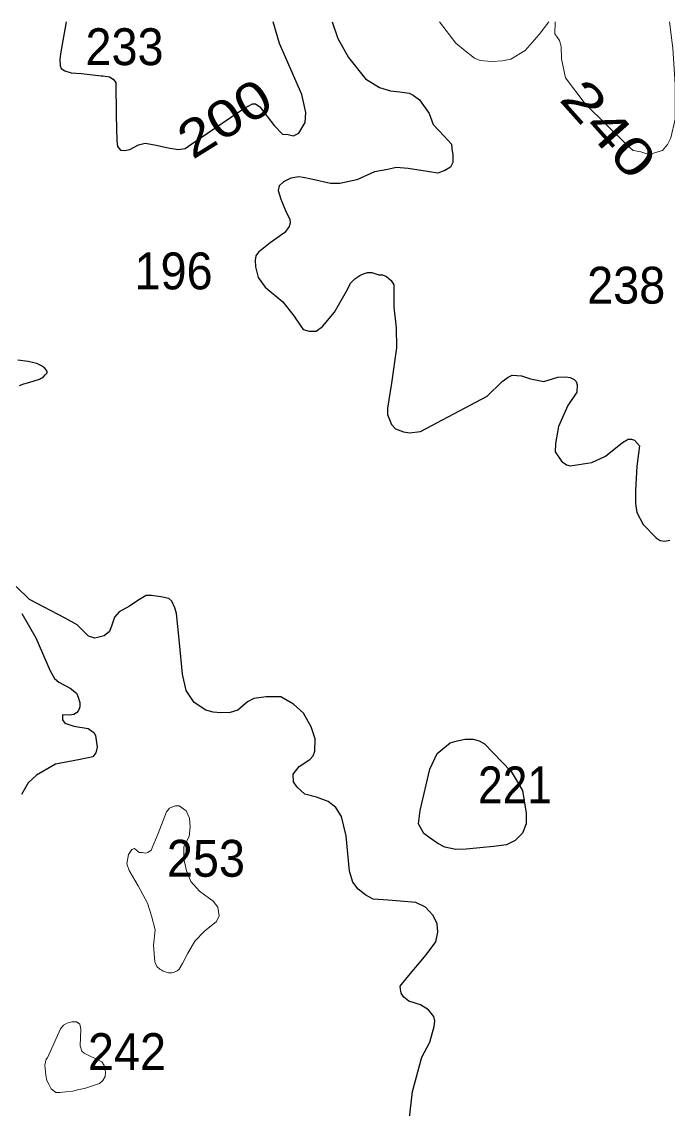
# Model space of a CAD drawing. Extents: x 445.4 to 500, y 8728.7 to 8784.
# Drawn here: x 486.89 to 489.693, y 8779.29 to 8784.005 of the extents above; entities that cross this region are included whole.
import ezdxf
from ezdxf.enums import TextEntityAlignment as Align

# ---------------------------------------------------------------- set-up
doc = ezdxf.new("R2010")
doc.units = 0
doc.header["$LTSCALE"] = 0.064
doc.layers.add('1', color=7, linetype='Continuous', lineweight=25)
doc.layers.add('2', color=7, linetype='Continuous', lineweight=13)
doc.layers.add('21', color=7, linetype='Continuous')
doc.layers.add('61', color=7, linetype='Continuous')

msp = doc.modelspace()

# ---------------------------------------------------------------- linework, layer by layer
at = {"layer": '1'}
for points in [[(487.0831, 8784.0041), (487.0589, 8783.8661), (487.0557, 8783.8406), (487.0573, 8783.8135), (487.0621, 8783.8023), (487.0781, 8783.7912), (487.1052, 8783.7832), (487.1499, 8783.78), (487.2346, 8783.7704), (487.2442, 8783.7704), (487.2713, 8783.7656), (487.2873, 8783.7561), (487.2985, 8783.7417), (487.3001, 8783.5981), (487.3034, 8783.4901), (487.3066, 8783.463), (487.3193, 8783.447), (487.3369, 8783.4455), (487.3593, 8783.4502), (487.3976, 8783.471), (487.4264, 8783.4774), (487.4663, 8783.471), (487.5254, 8783.4582), (487.5701, 8783.4502), (487.6005, 8783.455), (487.6292, 8783.4758), (487.8279, 8783.6107), (487.8599, 8783.6314), (487.8918, 8783.649), (487.9046, 8783.649), (487.9238, 8783.6362), (487.9861, 8783.5548), (488.0228, 8783.5166), (488.0468, 8783.515), (488.0707, 8783.5102), (488.0931, 8783.5213), (488.1202, 8783.5676), (488.1234, 8783.6107), (488.1059, 8783.6889), (488.01, 8783.9106), (487.982, 8784.0045)], [(488.2375, 8784.0046), (488.2627, 8783.9324), (488.3095, 8783.8491), (488.3828, 8783.7577), (488.4438, 8783.719), (488.4906, 8783.7048), (488.5313, 8783.7007), (488.572, 8783.6947), (488.5903, 8783.6865), (488.6168, 8783.6662), (488.6595, 8783.6073), (488.6758, 8783.5585), (488.7246, 8783.5077), (488.7557, 8783.4736), (488.7577, 8783.4553), (488.7618, 8783.4269), (488.7618, 8783.3943), (488.7516, 8783.374), (488.7272, 8783.3598), (488.6967, 8783.3476), (488.66, 8783.3537), (488.5685, 8783.3679), (488.5156, 8783.372), (488.479, 8783.3639), (488.422, 8783.3537), (488.3447, 8783.3191), (488.272, 8783.3028), (488.2313, 8783.3028), (488.1537, 8783.3203), (488.1118, 8783.3283), (488.0937, 8783.3316), (488.0586, 8783.326), (488.0269, 8783.3102), (488.0077, 8783.2932), (488.0043, 8783.2728), (488.0145, 8783.2355), (488.036, 8783.1858), (488.0541, 8783.1473), (488.0564, 8783.1304), (488.0518, 8783.1157), (488.0326, 8783.0897), (487.9689, 8783.0448), (487.918, 8783.0052), (487.9066, 8782.9894), (487.9044, 8782.9701), (487.9055, 8782.9419), (487.9168, 8782.8955), (487.9474, 8782.8525), (488.0233, 8782.7892), (488.071, 8782.7293), (488.1013, 8782.6839), (488.1121, 8782.6688), (488.1121, 8782.6688), (488.138, 8782.6623), (488.1553, 8782.6623), (488.1683, 8782.6623), (488.1964, 8782.6818), (488.2483, 8782.7444), (488.3067, 8782.8459), (488.3175, 8782.8697), (488.337, 8782.8891), (488.3586, 8782.9042), (488.3737, 8782.9107), (488.391, 8782.9172), (488.4105, 8782.9172), (488.4408, 8782.9064), (488.4559, 8782.9064), (488.4732, 8782.8999), (488.4948, 8782.8826), (488.5056, 8782.8632), (488.5056, 8782.766), (488.5153, 8782.6762), (488.5175, 8782.5898), (488.4959, 8782.4365), (488.4786, 8782.3285), (488.4786, 8782.3004), (488.4959, 8782.2572), (488.5132, 8782.2378), (488.5478, 8782.2248), (488.5737, 8782.2205), (488.6213, 8782.227), (488.911, 8782.3803), (488.9759, 8782.443), (489.0019, 8782.4624), (489.0192, 8782.4711), (489.0602, 8782.4689), (489.0992, 8782.4559), (489.1575, 8782.443), (489.2181, 8782.4624), (489.2527, 8782.4646), (489.2717, 8782.4616), (489.2881, 8782.4517), (489.2979, 8782.4435), (489.3012, 8782.4288), (489.2996, 8782.3976), (489.2618, 8782.3402), (489.2208, 8782.2485), (489.2077, 8782.1747), (489.206, 8782.1386), (489.2339, 8782.0976), (489.2553, 8782.0813)], [(486.8807, 8782.4267), (486.8991, 8782.4328), (486.9214, 8782.4389), (486.9438, 8782.446), (486.9682, 8782.4541), (486.9855, 8782.4633), (486.9926, 8782.4724), (487.0008, 8782.4816), (487.0008, 8782.4876), (486.9967, 8782.4948), (486.9886, 8782.5029), (486.9764, 8782.512), (486.956, 8782.5212), (486.9428, 8782.5252), (486.9184, 8782.5303), (486.8736, 8782.5364)], [(489.2553, 8782.0813), (489.2717, 8782.078), (489.3652, 8782.0927), (489.4243, 8782.119), (489.4982, 8782.1796), (489.5228, 8782.1927), (489.5375, 8782.1927), (489.5507, 8782.1894), (489.5507, 8782.1894), (489.572, 8782.1649), (489.5605, 8782.0763), (489.5542, 8781.9703), (489.5542, 8781.9146), (489.5608, 8781.8752), (489.5887, 8781.8228), (489.6445, 8781.7654), (489.6625, 8781.7539), (489.6822, 8781.7506), (489.7035, 8781.7556)], [(487.5885, 8781.1739), (487.5751, 8781.3089), (487.5623, 8781.4363), (487.5556, 8781.4613), (487.5423, 8781.4896), (487.5289, 8781.5013), (487.4939, 8781.5096), (487.4539, 8781.5146), (487.4305, 8781.5146), (487.3938, 8781.4929), (487.3588, 8781.468), (487.3138, 8781.4446), (487.2938, 8781.4213), (487.2821, 8781.3863), (487.2721, 8781.358), (487.2487, 8781.3397), (487.2071, 8781.3297), (487.1804, 8781.338), (487.1303, 8781.388), (487.0786, 8781.4163), (486.9235, 8781.4979), (486.8668, 8781.5546)], [(486.8902, 8781.4363), (486.9519, 8781.3314), (487.0136, 8781.1873), (487.0319, 8781.154), (487.0519, 8781.139), (487.1003, 8781.1123), (487.1286, 8781.0907), (487.1353, 8781.074), (487.142, 8781.0507), (487.142, 8781.0324), (487.137, 8781.0157), (487.1286, 8781.0057), (487.1169, 8780.999), (487.0969, 8780.9957), (487.0669, 8780.9974), (487.0669, 8780.9974), (487.0669, 8780.9757), (487.0769, 8780.9607), (487.1169, 8780.9474), (487.1786, 8780.9374), (487.2037, 8780.9207), (487.2103, 8780.9074), (487.2185, 8780.8565), (487.2118, 8780.8316), (487.1985, 8780.8149), (487.1434, 8780.8032), (487.0367, 8780.7832), (486.955, 8780.7349), (486.9183, 8780.7016), (486.89, 8780.6517)], [(488.568, 8779.1987), (488.5863, 8779.3619), (488.628, 8779.5118), (488.6615, 8779.5762), (488.6815, 8779.6445), (488.6832, 8779.6695), (488.6799, 8779.6878), (488.6565, 8779.7161), (488.6215, 8779.7378), (488.5715, 8779.7544), (488.5498, 8779.7711), (488.5381, 8779.7894), (488.5348, 8779.8061), (488.5331, 8779.8194), (488.5631, 8779.8577), (488.6465, 8779.956), (488.6883, 8780.0121), (488.6966, 8780.0538), (488.6933, 8780.0921), (488.675, 8780.1271), (488.6433, 8780.1621), (488.6016, 8780.1821), (488.4815, 8780.192), (488.4165, 8780.197), (488.3848, 8780.2137), (488.3514, 8780.2404), (488.3281, 8780.2703), (488.3131, 8780.3186), (488.2981, 8780.4719), (488.279, 8780.5565), (488.2539, 8780.5948), (488.2206, 8780.6215), (488.1706, 8780.6398), (488.1189, 8780.6531), (488.0855, 8780.6831), (488.0705, 8780.7064), (488.0688, 8780.7397), (488.0955, 8780.773), (488.1405, 8780.803), (488.1556, 8780.8197), (488.1622, 8780.8397), (488.1639, 8780.893), (488.1472, 8780.9446), (488.1138, 8781.004), (488.0704, 8781.044), (488.0154, 8781.0757), (487.952, 8781.0757), (487.8986, 8781.0673), (487.8703, 8781.054), (487.8286, 8781.0174), (487.7952, 8781.0074), (487.7552, 8781.0057), (487.7219, 8781.009), (487.6902, 8781.0174), (487.6385, 8781.0507), (487.6035, 8781.1023), (487.5885, 8781.1739)]]:
    msp.add_lwpolyline(points, dxfattribs=at)
msp.add_lwpolyline([(488.6624, 8780.761), (488.6941, 8780.8294), (488.7509, 8780.8761), (488.781, 8780.8845), (488.816, 8780.8912), (488.8495, 8780.8912), (488.8762, 8780.8845), (488.8996, 8780.8711), (489.0148, 8780.751), (489.0649, 8780.6692), (489.08, 8780.5708), (489.08, 8780.5241), (489.0649, 8780.484), (489.0332, 8780.4523), (488.9948, 8780.4323), (488.938, 8780.4256), (488.8194, 8780.414), (488.7743, 8780.4123), (488.7275, 8780.4223), (488.6974, 8780.439), (488.664, 8780.4624), (488.6356, 8780.4824), (488.6123, 8780.5241), (488.6206, 8780.5825)], close=True, dxfattribs=at)
at = {"layer": '2'}
for points in [[(488.7039, 8784.0048), (488.7748, 8783.9114), (488.8083, 8783.8852), (488.8561, 8783.8469), (488.8801, 8783.8374), (488.9303, 8783.8326), (488.9781, 8783.835), (489.014, 8783.8422), (489.0762, 8783.8804), (489.1361, 8783.9497), (489.1789, 8784.0049)], [(489.2057, 8784.0049), (489.2054, 8783.9521), (489.2246, 8783.9234), (489.2318, 8783.8971), (489.2342, 8783.8445), (489.2509, 8783.7609), (489.337, 8783.6486), (489.5213, 8783.467), (489.5452, 8783.4455), (489.5787, 8783.4408), (489.6122, 8783.4288), (489.6481, 8783.4384), (489.672, 8783.4455), (489.6935, 8783.4718), (489.7079, 8783.5005), (489.727, 8783.5817), (489.727, 8783.7322), (489.7175, 8783.8899), (489.7029, 8784.005)]]:
    msp.add_lwpolyline(points, dxfattribs=at)
for points in [[(487.3466, 8780.3502), (487.3533, 8780.3903), (487.3533, 8780.3903), (487.3689, 8780.4127), (487.3801, 8780.4171), (487.3801, 8780.4171), (487.4002, 8780.3993), (487.4136, 8780.3993), (487.427, 8780.397), (487.4382, 8780.3993), (487.4516, 8780.4104), (487.4829, 8780.4819), (487.5187, 8780.5756), (487.5321, 8780.5913), (487.5321, 8780.5913), (487.5567, 8780.6024), (487.5567, 8780.6024), (487.5745, 8780.6024), (487.6036, 8780.5801), (487.6192, 8780.5488), (487.6215, 8780.5109), (487.617, 8780.4685), (487.5946, 8780.4261), (487.5944, 8780.3726), (487.606, 8780.3198), (487.6241, 8780.2737), (487.6621, 8780.2324), (487.7215, 8780.1879), (487.7413, 8780.1616), (487.7479, 8780.1253), (487.7364, 8780.1006), (487.6836, 8780.0577), (487.6419, 8780.0152), (487.6097, 8779.9592), (487.5887, 8779.918), (487.5735, 8779.8927), (487.5656, 8779.8855), (487.5497, 8779.879), (487.5424, 8779.8768), (487.5279, 8779.8775), (487.5171, 8779.8797), (487.5171, 8779.8797), (487.5041, 8779.8848), (487.4954, 8779.8906), (487.4896, 8779.8934), (487.4773, 8779.905), (487.4686, 8779.9253), (487.4628, 8779.9968), (487.4701, 8780.064), (487.4534, 8780.1246), (487.436, 8780.1796), (487.3955, 8780.2555), (487.3564, 8780.3211)], [(487.0023, 8779.5089), (487.059, 8779.634), (487.0724, 8779.6507), (487.0874, 8779.659), (487.1075, 8779.664), (487.1275, 8779.664), (487.1426, 8779.654), (487.1476, 8779.6323), (487.1442, 8779.5606), (487.1515, 8779.538), (487.161, 8779.5286), (487.1852, 8779.517), (487.2126, 8779.5043), (487.2379, 8779.4907), (487.2484, 8779.4749), (487.2526, 8779.457), (487.2537, 8779.4444), (487.2526, 8779.4275), (487.2431, 8779.4096), (487.2273, 8779.397), (487.1631, 8779.376), (487.1388, 8779.3707), (487.1125, 8779.3644), (487.0819, 8779.3602), (487.0556, 8779.3581), (487.0387, 8779.3581), (487.0177, 8779.3739), (487.0092, 8779.3907), (486.9987, 8779.4107), (486.9945, 8779.4338), (486.9913, 8779.477), (486.9966, 8779.5033)]]:
    msp.add_lwpolyline(points, close=True, dxfattribs=at)

# ---------------------------------------------------------------- texts
at = {"layer": '21', "width": 0.95}
msp.add_text('233', height=0.16, dxfattribs=at).set_placement((487.5061, 8783.8166), align=Align.RIGHT)
at = {"layer": '21'}
for s, width, p in [('196', 0.95, (487.3799, 8782.8435)), ('238', 0.95, (489.345, 8782.7815)), ('221', 0.9, (488.8711, 8780.6129)), ('253', 0.95, (487.5204, 8780.2943)), ('242', 0.95, (487.1778, 8779.4554))]:
    msp.add_text(s, height=0.16, dxfattribs=dict(at, width=width)).set_placement(p)
at = {"layer": '61'}
for s, rotation, width, p in [('200', 32.018, 1.2, (487.8136, 8783.5178)), ('240', 311.806, 1.35, (489.3794, 8783.4866))]:
    msp.add_text(s, height=0.16, rotation=rotation, dxfattribs=dict(at, width=width)).set_placement(p, align=Align.CENTER)

doc.saveas('drawing.dxf')
